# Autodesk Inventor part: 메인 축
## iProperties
Created: 2012-05
Part Number: 메인 축
Document SubType Name: 모델링
Designer: SeoGD™
Mass: 168.567 g
Surface Area: 72.5109 cm^2
Volume: 21.4462 cm^3
Density: 7.86 g/cm^3
Material: 강, 연강
변환 표준: STEP AP214IS
파일 이름: C:\Users\SeoGD\Desktop\?쒗뿕\硫붿씤 異?.stp
전처리기: Build: 253, Release: 2010 SP1 - Date: Wed 07/29/2009
전송 단위: 밀리미터
불확실성: 0.01
Author: SeoGD™
